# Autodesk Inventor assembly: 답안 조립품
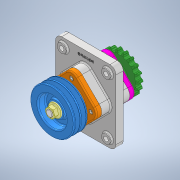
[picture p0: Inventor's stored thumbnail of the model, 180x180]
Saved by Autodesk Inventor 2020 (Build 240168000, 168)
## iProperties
Created: 2021-07
Part Number: 답안 조립품
Document SubType Name: Assembly
Designer: Owner
Author: Owner
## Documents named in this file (16)
- C:\Users\Owner\Desktop\710707V1021\710707V1021\답안 조립품.iam
- C:\Users\Owner\Desktop\710707V1021\710707V1021\본체.ipt
- C:\Users\Owner\Desktop\710707V1021\710707V1021\M16 너트.ipt
- C:\Users\Owner\Desktop\710707V1021\710707V1021\V-벨트풀리.ipt
- C:\Users\Owner\Desktop\710707V1021\710707V1021\멈춤나사 M4.ipt
- C:\Users\Owner\Desktop\710707V1021\710707V1021\베어링 6206.ipt
- C:\Users\Owner\Desktop\710707V1021\710707V1021\볼트 M6.ipt
- C:\Users\Owner\Desktop\710707V1021\710707V1021\부시.ipt
- C:\Users\Owner\Desktop\710707V1021\710707V1021\오일실 30x42x8.ipt
- C:\Users\Owner\Desktop\710707V1021\710707V1021\오일실 30x45x8.ipt
- C:\Users\Owner\Desktop\710707V1021\710707V1021\체인 스프로킷.ipt
- C:\Users\Owner\Desktop\710707V1021\710707V1021\축.ipt
- C:\Users\Owner\Desktop\710707V1021\710707V1021\커버A.ipt
- C:\Users\Owner\Desktop\710707V1021\710707V1021\커버B.ipt
- C:\Users\Owner\Desktop\710707V1021\710707V1021\키 6x6x18.ipt
- C:\Users\Owner\Desktop\710707V1021\710707V1021\키 6x6x20.ipt
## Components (3 placed, 2 different names)
1. M16 너트:1
2. V-벨트풀리:1 — 각도:2
3. M16 너트:2
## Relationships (1: Angle 1)
- 각도:2 [Angle]: V-벨트풀리:1
